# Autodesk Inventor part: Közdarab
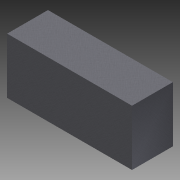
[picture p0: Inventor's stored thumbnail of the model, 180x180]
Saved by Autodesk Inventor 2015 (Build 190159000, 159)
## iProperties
Created: 2013-02
Part Number: Közdarab
Material: Generic
Document SubType Name: Modeling
Designer: Marci
Density: 1 g/cm^3
Appearance: Honed - Dark Gray
Author: Marci
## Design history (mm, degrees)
sketch "Sketch1"
  geometry: L1 (0, 0)-(55, 0); L2 (55, 0)-(55, 18); L3 (55, 18)-(0, 18); L4 (0, 18)-(0, 0)
  constraints: 8 end point, 2 parallel, 1 horizontal, 1 perpendicular
  dimensions: "d0" = 55 distance of L1.start L1.end; "d1" = 18 distance of L1.end L2.end
extrude "Extrusion1" new body sketch "Sketch1" distance "d2" = 24.5; taper "d3" = 0 deg
body "Solid1"
